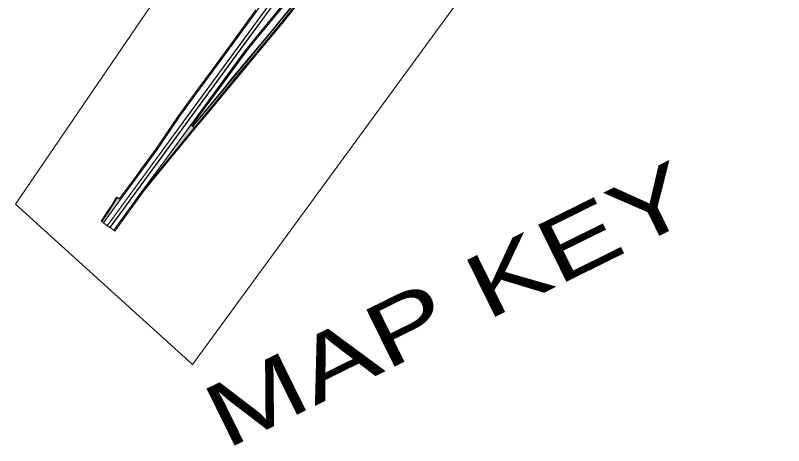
# Model space of a CAD drawing. Extents: x 2356431 to 2371438, y 6972864 to 6982525.
# Drawn here: x 2369855 to 2370119.6, y 6980058 to 6980206.1 of the extents above; entities that cross this region are included whole.
import ezdxf

# ---------------------------------------------------------------- set-up
doc = ezdxf.new("R2010")
doc.units = 0
doc.header["$LTSCALE"] = 5.6
for name, color, linetype, lineweight in [('1', 7, 'Continuous', 25), ('10', 7, 'Continuous', 13), ('11', 7, 'Continuous', 13), ('62', 7, 'Continuous', 25)]:
    doc.layers.add(name, color=color, linetype=linetype, lineweight=lineweight)

msp = doc.modelspace()

# ---------------------------------------------------------------- hatches: boundary and pattern name
at = {"layer": '10'}
msp.add_hatch(color=256, dxfattribs=at).paths.add_polyline_path([(2369884.562, 6980135.284), (2369886.684, 6980138.477), (2369888.225, 6980140.821), (2369889.833, 6980143.559), (2369890.064, 6980143.416), (2369888.697, 6980141.088), (2369887.332, 6980138.991), (2369884.791, 6980135.111)])
at = {"layer": '11'}
for points in [[(2369916.699, 6980167.482), (2369915.466, 6980168.388), (2369906.515, 6980156.192), (2369897.866, 6980144.517)], [(2369890.656, 6980143.064), (2369890.661, 6980143.137), (2369890.683, 6980142.963), (2369891.23, 6980142.681), (2369885.369, 6980134.707), (2369884.781, 6980135.126), (2369886.972, 6980138.414), (2369888.044, 6980140.047), (2369888.879, 6980141.478), (2369889.67, 6980142.719), (2369890.09, 6980143.364)]]:
    msp.add_hatch(color=256, dxfattribs=at).paths.add_polyline_path(points)

# ---------------------------------------------------------------- linework, layer by layer
at = {"layer": '1', "lineweight": 13}
msp.add_lwpolyline([(2369855.033, 6980141.088), (2370017.862, 6980379.583), (2370022.31, 6980590.536), (2370099.424, 6980609.051), (2370119.624, 6980364.065), (2369916.007, 6980085.895)], close=True, dxfattribs=at)
at = {"layer": '10'}
for points in [[(2370001.914, 6980292.618), (2370003.267, 6980294.031), (2370004.678, 6980295.5), (2370007.223, 6980298.09), (2369998.46, 6980286.086), (2369991.023, 6980275.961), (2369886.641, 6980133.705), (2369885.369, 6980134.707), (2369891.23, 6980142.681), (2369903.963, 6980160.048), (2369911.523, 6980171.262), (2369937.839, 6980207.148), (2369944.978, 6980217.321), (2369950.606, 6980226.08), (2369951.596, 6980225.566), (2369952.33, 6980225.047)], [(2369886.641, 6980133.703), (2369900.491, 6980152.536), (2369914.387, 6980171.581), (2369934.283, 6980198.661), (2369953.969, 6980225.51), (2369968.717, 6980245.608), (2369980.705, 6980261.924), (2369990.814, 6980275.818), (2369991.335, 6980274.682), (2369984.112, 6980264.411), (2369980.974, 6980259.77), (2369968.161, 6980242.702), (2369951.268, 6980219.945), (2369934.994, 6980197.786), (2369887.62, 6980133.064)], [(2369915.459, 6980168.394), (2369924.956, 6980181.32), (2369934.943, 6980194.903), (2369937.976, 6980198.55), (2369947.309, 6980209.893), (2369956.288, 6980220.766), (2369959.635, 6980224.826), (2369965.762, 6980232.283), (2369969.164, 6980236.639), (2369973.244, 6980242.135), (2369979.086, 6980249.941), (2369979.431, 6980249.694), (2369976.222, 6980245.39), (2369973.695, 6980241.987), (2369968.649, 6980235.267), (2369966.22, 6980232.195), (2369961.268, 6980226.112), (2369955.536, 6980219.16), (2369946.572, 6980208.31), (2369941.09, 6980201.636), (2369935.408, 6980194.756), (2369930.575, 6980188.234), (2369924.993, 6980180.621), (2369915.852, 6980168.166)], [(2369944.268, 6980210.24), (2369918.813, 6980175.589), (2369905.902, 6980157.956), (2369901.464, 6980151.872), (2369887.652, 6980133.075), (2369888.966, 6980132.131), (2369897.866, 6980144.517), (2369906.515, 6980156.192), (2369933.995, 6980193.657), (2369934.998, 6980194.96), (2369939.237, 6980200.145), (2369946.256, 6980208.623)], [(2369884.562, 6980135.284), (2369886.684, 6980138.477), (2369888.225, 6980140.821), (2369889.833, 6980143.559), (2369890.064, 6980143.416), (2369888.697, 6980141.088), (2369887.332, 6980138.991), (2369884.791, 6980135.111)]]:
    msp.add_lwpolyline(points, close=True, dxfattribs=at)
for points in [[(2369952.218, 6980209.932), (2369946.982, 6980203.415), (2369939.49, 6980194.388), (2369930.167, 6980183.151), (2369921.291, 6980172.488), (2369916.973, 6980167.227), (2369913.909, 6980163.543), (2369903.432, 6980150.769), (2369899.032, 6980145.369), (2369889.336, 6980131.875), (2369888.988, 6980132.139), (2369897.755, 6980144.362), (2369900.358, 6980147.551), (2369901.595, 6980149.08), (2369906.684, 6980155.27), (2369916.714, 6980167.493), (2369923.362, 6980175.54), (2369932.276, 6980186.281), (2369937.756, 6980192.871), (2369947.054, 6980204.073), (2369951.504, 6980209.593)], [(2369950.79, 6980209.699), (2369947.319, 6980205.398), (2369942.433, 6980199.501), (2369937.494, 6980193.562), (2369927.894, 6980181.987), (2369916.197, 6980167.882), (2369916.064, 6980167.976), (2369918.633, 6980171.067), (2369921.417, 6980174.443), (2369924.612, 6980178.309), (2369926.896, 6980181.037), (2369928.833, 6980183.394), (2369933.515, 6980189.039), (2369943.106, 6980200.585), (2369947.656, 6980206.064), (2369949.59, 6980208.467)], [(2369938.039, 6980207.426), (2369926.453, 6980191.646), (2369917.158, 6980178.961), (2369911.912, 6980171.822), (2369909.436, 6980168.195), (2369906.291, 6980163.511), (2369903.799, 6980159.787), (2369891.225, 6980142.73), (2369890.751, 6980142.942), (2369895.801, 6980149.658), (2369898.516, 6980153.394), (2369903.413, 6980160.023), (2369906.311, 6980164.313), (2369911.075, 6980171.379), (2369914.087, 6980175.479), (2369917.917, 6980180.719), (2369922.79, 6980187.39), (2369929.105, 6980195.995), (2369937.894, 6980207.975)]]:
    msp.add_lwpolyline(points, dxfattribs=at)
at = {"layer": '11'}
msp.add_lwpolyline([(2369950.89, 6980209.799), (2369945.226, 6980202.862), (2369935.214, 6980190.789), (2369927.508, 6980181.466), (2369916.221, 6980167.916), (2369916.191, 6980167.856), (2369916.699, 6980167.482), (2369924.269, 6980176.6), (2369929.81, 6980183.276), (2369934.481, 6980188.941), (2369939.909, 6980195.462), (2369943.777, 6980200.14), (2369949.553, 6980207.13)], dxfattribs=at)
for points in [[(2369916.699, 6980167.482), (2369915.466, 6980168.388), (2369906.515, 6980156.192), (2369897.866, 6980144.517)], [(2369890.656, 6980143.064), (2369890.661, 6980143.137), (2369890.683, 6980142.963), (2369891.23, 6980142.681), (2369885.369, 6980134.707), (2369884.781, 6980135.126), (2369886.972, 6980138.414), (2369888.044, 6980140.047), (2369888.879, 6980141.478), (2369889.67, 6980142.719), (2369890.09, 6980143.364)]]:
    msp.add_lwpolyline(points, close=True, dxfattribs=at)

# ---------------------------------------------------------------- texts
at = {"layer": '62', "width": 1.4}
msp.add_text('MAP KEY', height=21.87, rotation=26.268, dxfattribs=at).set_placement((2369927.536, 6980056.549))

doc.saveas('drawing.dxf')
